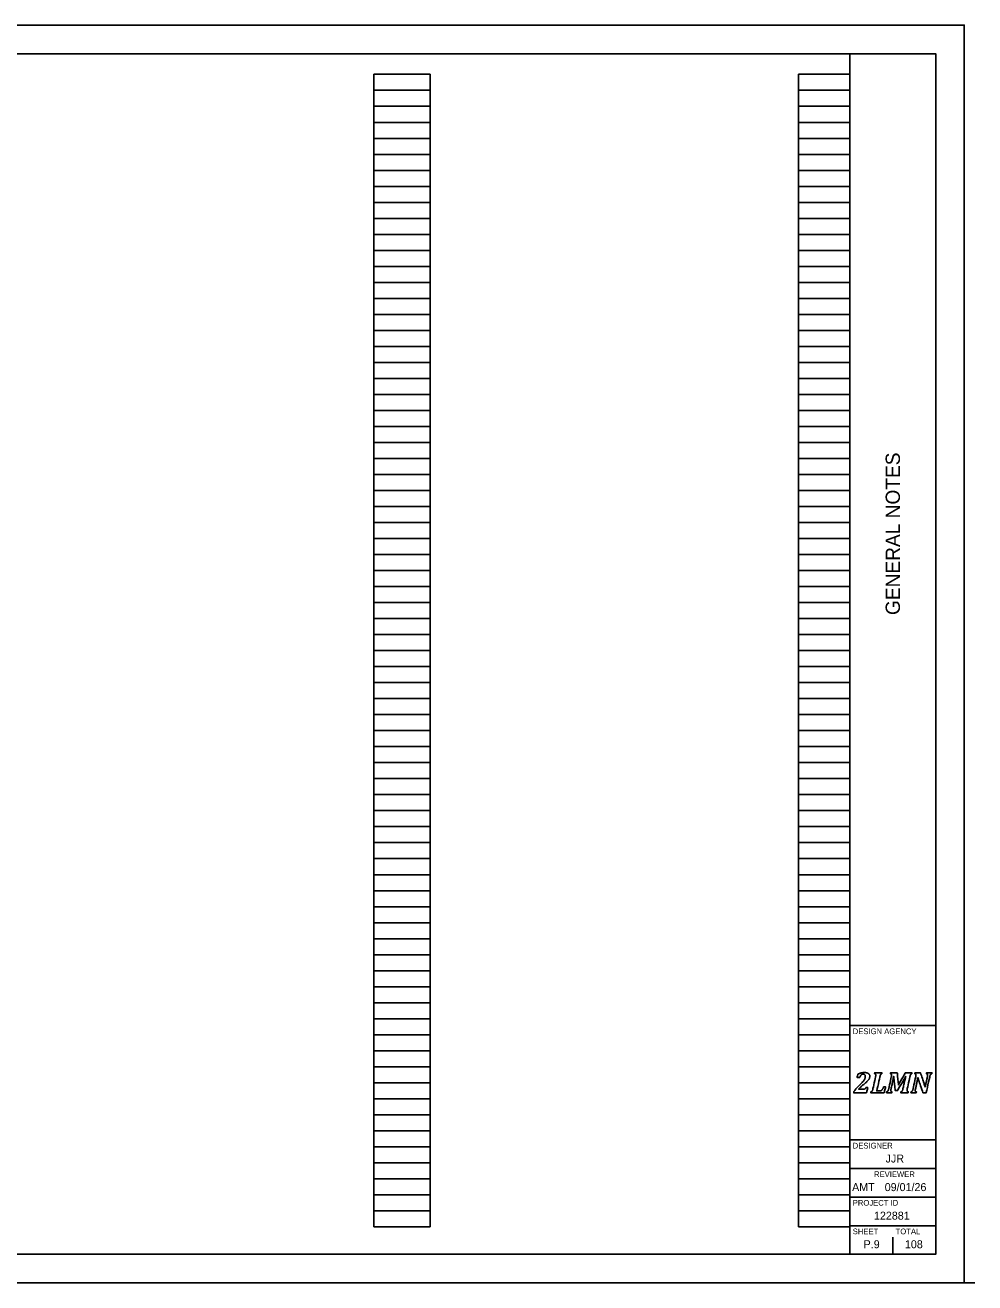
# Model space of a CAD drawing. Extents: x 0 to 34.2, y 0 to 22.
# Drawn here: x 17.58 to 34.18, y 0 to 22 of the extents above; entities that cross this region are included whole.
import ezdxf

# ---------------------------------------------------------------- set-up
doc = ezdxf.new("R2010")
doc.units = 0
for name, color, linetype in [('SH_Border', 7, 'Continuous'), ('SH_Cut_Line', 7, 'Continuous'), ('SH_Data', 7, 'Continuous'), ('SH_Text', 7, 'Continuous')]:
    doc.layers.add(name, color=color, linetype=linetype)

msp = doc.modelspace()

# ---------------------------------------------------------------- linework, layer by layer
at = {"layer": 'SH_Border'}
for p, q in [((32, 0.5), (32, 21.5)), ((32, 4.5), (33.5, 4.5)), ((32, 2.5), (33.5, 2.5)), ((32, 2), (33.5, 2)), ((32, 1.5), (33.5, 1.5)), ((32, 1), (33.5, 1))]:
    msp.add_line(p, q, dxfattribs=at)
msp.add_lwpolyline([(1.5, 21.5), (33.5, 21.5), (33.5, 0.5), (1.5, 0.5)], close=True, dxfattribs=at)
at = {"layer": 'SH_Cut_Line'}
msp.add_lwpolyline([(0, 0), (34, 0), (34, 22), (0, 22)], close=True, dxfattribs=at)
at = {"layer": 'SH_Data'}
for p, q in [((23.68, 0.98), (23.68, 21.14)), ((23.68, 21.14), (24.66, 21.14)), ((24.66, 0.98), (24.66, 21.14)), ((31.1, 0.98), (31.1, 21.14)), ((31.1, 21.14), (32, 21.14)), ((32, 0.98), (32, 21.14)), ((23.68, 20.86), (24.66, 20.86)), ((31.1, 20.86), (32, 20.86)), ((23.68, 20.58), (24.66, 20.58)), ((31.1, 20.58), (32, 20.58)), ((23.68, 20.3), (24.66, 20.3)), ((31.1, 20.3), (32, 20.3)), ((23.68, 20.02), (24.66, 20.02)), ((31.1, 20.02), (32, 20.02)), ((23.68, 19.74), (24.66, 19.74)), ((31.1, 19.74), (32, 19.74)), ((23.68, 19.46), (24.66, 19.46)), ((31.1, 19.46), (32, 19.46)), ((23.68, 19.18), (24.66, 19.18)), ((31.1, 19.18), (32, 19.18)), ((23.68, 18.9), (24.66, 18.9)), ((31.1, 18.9), (32, 18.9)), ((23.68, 18.62), (24.66, 18.62)), ((31.1, 18.62), (32, 18.62)), ((23.68, 18.34), (24.66, 18.34)), ((31.1, 18.34), (32, 18.34)), ((23.68, 18.06), (24.66, 18.06)), ((31.1, 18.06), (32, 18.06)), ((23.68, 17.78), (24.66, 17.78)), ((31.1, 17.78), (32, 17.78)), ((23.68, 17.5), (24.66, 17.5)), ((31.1, 17.5), (32, 17.5)), ((23.68, 17.22), (24.66, 17.22)), ((31.1, 17.22), (32, 17.22)), ((23.68, 16.94), (24.66, 16.94)), ((31.1, 16.94), (32, 16.94)), ((23.68, 16.66), (24.66, 16.66)), ((31.1, 16.66), (32, 16.66)), ((23.68, 16.38), (24.66, 16.38)), ((31.1, 16.38), (32, 16.38)), ((23.68, 16.1), (24.66, 16.1)), ((31.1, 16.1), (32, 16.1)), ((23.68, 15.82), (24.66, 15.82)), ((31.1, 15.82), (32, 15.82)), ((23.68, 15.54), (24.66, 15.54)), ((31.1, 15.54), (32, 15.54)), ((23.68, 15.26), (24.66, 15.26)), ((31.1, 15.26), (32, 15.26)), ((23.68, 14.98), (24.66, 14.98)), ((31.1, 14.98), (32, 14.98)), ((23.68, 14.7), (24.66, 14.7)), ((31.1, 14.7), (32, 14.7)), ((23.68, 14.42), (24.66, 14.42)), ((31.1, 14.42), (32, 14.42)), ((23.68, 14.14), (24.66, 14.14)), ((31.1, 14.14), (32, 14.14)), ((23.68, 13.86), (24.66, 13.86)), ((31.1, 13.86), (32, 13.86)), ((23.68, 13.58), (24.66, 13.58)), ((31.1, 13.58), (32, 13.58)), ((23.68, 13.3), (24.66, 13.3)), ((31.1, 13.3), (32, 13.3)), ((23.68, 13.02), (24.66, 13.02)), ((31.1, 13.02), (32, 13.02)), ((23.68, 12.74), (24.66, 12.74)), ((31.1, 12.74), (32, 12.74)), ((23.68, 12.46), (24.66, 12.46)), ((31.1, 12.46), (32, 12.46)), ((23.68, 12.18), (24.66, 12.18)), ((31.1, 12.18), (32, 12.18)), ((23.68, 11.9), (24.66, 11.9)), ((31.1, 11.9), (32, 11.9)), ((23.68, 11.62), (24.66, 11.62)), ((31.1, 11.62), (32, 11.62)), ((23.68, 11.34), (24.66, 11.34)), ((31.1, 11.34), (32, 11.34)), ((23.68, 11.06), (24.66, 11.06)), ((31.1, 11.06), (32, 11.06)), ((23.68, 10.78), (24.66, 10.78)), ((31.1, 10.78), (32, 10.78)), ((23.68, 10.5), (24.66, 10.5)), ((31.1, 10.5), (32, 10.5)), ((23.68, 10.22), (24.66, 10.22)), ((31.1, 10.22), (32, 10.22)), ((23.68, 9.94), (24.66, 9.94)), ((31.1, 9.94), (32, 9.94)), ((23.68, 9.66), (24.66, 9.66)), ((31.1, 9.66), (32, 9.66)), ((23.68, 9.38), (24.66, 9.38)), ((31.1, 9.38), (32, 9.38)), ((23.68, 9.1), (24.66, 9.1)), ((31.1, 9.1), (32, 9.1)), ((23.68, 8.82), (24.66, 8.82)), ((31.1, 8.82), (32, 8.82)), ((23.68, 8.54), (24.66, 8.54)), ((31.1, 8.54), (32, 8.54)), ((23.68, 8.26), (24.66, 8.26)), ((31.1, 8.26), (32, 8.26)), ((23.68, 7.98), (24.66, 7.98)), ((31.1, 7.98), (32, 7.98)), ((23.68, 7.7), (24.66, 7.7)), ((31.1, 7.7), (32, 7.7)), ((23.68, 7.42), (24.66, 7.42)), ((31.1, 7.42), (32, 7.42)), ((23.68, 7.14), (24.66, 7.14)), ((31.1, 7.14), (32, 7.14)), ((23.68, 6.86), (24.66, 6.86)), ((31.1, 6.86), (32, 6.86)), ((23.68, 6.58), (24.66, 6.58)), ((31.1, 6.58), (32, 6.58)), ((23.68, 6.3), (24.66, 6.3)), ((31.1, 6.3), (32, 6.3)), ((23.68, 6.02), (24.66, 6.02)), ((31.1, 6.02), (32, 6.02)), ((23.68, 5.74), (24.66, 5.74)), ((31.1, 5.74), (32, 5.74)), ((23.68, 5.46), (24.66, 5.46)), ((31.1, 5.46), (32, 5.46)), ((23.68, 5.18), (24.66, 5.18)), ((31.1, 5.18), (32, 5.18)), ((23.68, 4.9), (24.66, 4.9)), ((31.1, 4.9), (32, 4.9)), ((23.68, 4.62), (24.66, 4.62)), ((31.1, 4.62), (32, 4.62)), ((23.68, 4.34), (24.66, 4.34)), ((31.1, 4.34), (32, 4.34)), ((23.68, 4.06), (24.66, 4.06)), ((31.1, 4.06), (32, 4.06)), ((23.68, 3.78), (24.66, 3.78)), ((31.1, 3.78), (32, 3.78)), ((23.68, 3.5), (24.66, 3.5)), ((31.1, 3.5), (32, 3.5)), ((32.75, 3.5), (32.75, 3.5)), ((23.68, 3.22), (24.66, 3.22)), ((31.1, 3.22), (32, 3.22)), ((23.68, 2.94), (24.66, 2.94)), ((31.1, 2.94), (32, 2.94)), ((23.68, 2.66), (24.66, 2.66)), ((31.1, 2.66), (32, 2.66)), ((23.68, 2.38), (24.66, 2.38)), ((31.1, 2.38), (32, 2.38)), ((23.68, 2.1), (24.66, 2.1)), ((31.1, 2.1), (32, 2.1)), ((23.68, 1.82), (24.66, 1.82)), ((31.1, 1.82), (32, 1.82)), ((23.68, 1.54), (24.66, 1.54)), ((31.1, 1.54), (32, 1.54)), ((23.68, 1.26), (24.66, 1.26)), ((31.1, 1.26), (32, 1.26)), ((23.68, 0.98), (24.66, 0.98)), ((31.1, 0.98), (32, 0.98)), ((32.375, 0.675), (32.375, 0.675)), ((32.75, 0.5), (32.75, 0.8))]:
    msp.add_line(p, q, dxfattribs=at)
for points in [[(32.237, 3.388), (32.246, 3.388), (32.253, 3.389), (32.258, 3.39), (32.263, 3.392), (32.267, 3.394), (32.27, 3.397), (32.273, 3.401), (32.277, 3.408), (32.281, 3.417), (32.281, 3.417), (32.312, 3.417), (32.312, 3.417), (32.312, 3.417), (32.29, 3.326), (32.29, 3.326), (32.29, 3.326), (32.066, 3.326), (32.066, 3.326), (32.066, 3.326), (32.069, 3.343), (32.069, 3.343), (32.078, 3.358), (32.091, 3.375), (32.106, 3.394), (32.122, 3.412), (32.144, 3.435), (32.172, 3.462), (32.197, 3.486), (32.217, 3.506), (32.23, 3.521), (32.243, 3.537), (32.253, 3.551), (32.259, 3.566), (32.266, 3.58), (32.269, 3.595), (32.269, 3.61), (32.269, 3.622), (32.266, 3.632), (32.26, 3.64), (32.253, 3.647), (32.245, 3.65), (32.234, 3.65), (32.22, 3.65), (32.208, 3.646), (32.198, 3.636), (32.188, 3.627), (32.18, 3.613), (32.172, 3.593), (32.172, 3.593), (32.126, 3.593), (32.126, 3.593), (32.126, 3.593), (32.14, 3.654), (32.14, 3.654), (32.166, 3.663), (32.188, 3.669), (32.205, 3.673), (32.223, 3.676), (32.24, 3.678), (32.258, 3.678), (32.278, 3.678), (32.295, 3.675), (32.309, 3.669), (32.322, 3.664), (32.332, 3.656), (32.339, 3.646), (32.345, 3.637), (32.348, 3.626), (32.348, 3.613), (32.348, 3.602), (32.346, 3.591), (32.342, 3.581), (32.339, 3.571), (32.333, 3.56), (32.324, 3.549), (32.315, 3.539), (32.304, 3.526), (32.289, 3.513), (32.275, 3.499), (32.254, 3.482), (32.228, 3.46), (32.216, 3.45), (32.202, 3.438), (32.188, 3.425), (32.174, 3.412), (32.162, 3.4), (32.154, 3.391), (32.154, 3.391), (32.153, 3.388), (32.153, 3.388), (32.153, 3.388), (32.237, 3.388), (32.237, 3.388)], [(32.237, 3.388), (32.237, 3.388), (32.153, 3.388), (32.153, 3.388), (32.153, 3.388), (32.154, 3.391), (32.154, 3.391), (32.162, 3.4), (32.174, 3.412), (32.188, 3.425), (32.202, 3.438), (32.216, 3.45), (32.228, 3.46), (32.254, 3.482), (32.275, 3.499), (32.289, 3.513), (32.304, 3.526), (32.315, 3.539), (32.324, 3.549), (32.333, 3.56), (32.339, 3.571), (32.342, 3.581), (32.346, 3.591), (32.348, 3.602), (32.348, 3.613), (32.348, 3.626), (32.345, 3.637), (32.339, 3.646), (32.332, 3.656), (32.322, 3.664), (32.309, 3.669), (32.295, 3.675), (32.278, 3.678), (32.258, 3.678), (32.24, 3.678), (32.223, 3.676), (32.205, 3.673), (32.188, 3.669), (32.166, 3.663), (32.14, 3.654), (32.14, 3.654), (32.126, 3.593), (32.126, 3.593), (32.126, 3.593), (32.172, 3.593), (32.172, 3.593), (32.18, 3.613), (32.188, 3.627), (32.198, 3.636), (32.208, 3.646), (32.22, 3.65), (32.234, 3.65), (32.245, 3.65), (32.253, 3.647), (32.26, 3.64), (32.266, 3.632), (32.269, 3.622), (32.269, 3.61), (32.269, 3.595), (32.266, 3.58), (32.259, 3.566), (32.253, 3.551), (32.243, 3.537), (32.23, 3.521), (32.217, 3.506), (32.197, 3.486), (32.172, 3.462), (32.144, 3.435), (32.122, 3.412), (32.106, 3.394), (32.091, 3.375), (32.078, 3.358), (32.069, 3.343), (32.069, 3.343), (32.066, 3.326), (32.066, 3.326), (32.066, 3.326), (32.29, 3.326), (32.29, 3.326), (32.29, 3.326), (32.312, 3.417), (32.312, 3.417), (32.312, 3.417), (32.281, 3.417), (32.281, 3.417), (32.277, 3.408), (32.273, 3.401), (32.27, 3.397), (32.267, 3.394), (32.263, 3.392), (32.258, 3.39), (32.253, 3.389), (32.246, 3.388), (32.237, 3.388)], [(32.518, 3.356), (32.527, 3.356), (32.533, 3.357), (32.538, 3.358), (32.542, 3.36), (32.546, 3.362), (32.55, 3.365), (32.554, 3.368), (32.558, 3.372), (32.562, 3.377), (32.567, 3.382), (32.571, 3.388), (32.576, 3.397), (32.58, 3.405), (32.585, 3.415), (32.589, 3.427), (32.589, 3.427), (32.624, 3.427), (32.624, 3.427), (32.624, 3.427), (32.598, 3.326), (32.598, 3.326), (32.598, 3.326), (32.365, 3.326), (32.365, 3.326), (32.365, 3.326), (32.369, 3.343), (32.369, 3.343), (32.376, 3.345), (32.381, 3.348), (32.385, 3.351), (32.389, 3.355), (32.392, 3.36), (32.395, 3.366), (32.398, 3.373), (32.4, 3.382), (32.403, 3.395), (32.403, 3.395), (32.449, 3.605), (32.449, 3.605), (32.452, 3.615), (32.453, 3.625), (32.453, 3.635), (32.453, 3.642), (32.451, 3.647), (32.448, 3.651), (32.444, 3.654), (32.439, 3.656), (32.432, 3.657), (32.432, 3.657), (32.435, 3.674), (32.435, 3.674), (32.435, 3.674), (32.563, 3.674), (32.563, 3.674), (32.563, 3.674), (32.559, 3.657), (32.559, 3.657), (32.552, 3.655), (32.547, 3.652), (32.543, 3.649), (32.539, 3.645), (32.536, 3.64), (32.533, 3.634), (32.531, 3.627), (32.528, 3.618), (32.525, 3.605), (32.525, 3.605), (32.47, 3.356), (32.47, 3.356), (32.47, 3.356), (32.518, 3.356), (32.518, 3.356)], [(32.518, 3.356), (32.518, 3.356), (32.47, 3.356), (32.47, 3.356), (32.47, 3.356), (32.525, 3.605), (32.525, 3.605), (32.528, 3.618), (32.531, 3.627), (32.533, 3.634), (32.536, 3.64), (32.539, 3.645), (32.543, 3.649), (32.547, 3.652), (32.552, 3.655), (32.559, 3.657), (32.559, 3.657), (32.563, 3.674), (32.563, 3.674), (32.563, 3.674), (32.435, 3.674), (32.435, 3.674), (32.435, 3.674), (32.432, 3.657), (32.432, 3.657), (32.439, 3.656), (32.444, 3.654), (32.448, 3.651), (32.451, 3.647), (32.453, 3.642), (32.453, 3.635), (32.453, 3.625), (32.452, 3.615), (32.449, 3.605), (32.449, 3.605), (32.403, 3.395), (32.403, 3.395), (32.4, 3.382), (32.398, 3.373), (32.395, 3.366), (32.392, 3.36), (32.389, 3.355), (32.385, 3.351), (32.381, 3.348), (32.376, 3.345), (32.369, 3.343), (32.369, 3.343), (32.365, 3.326), (32.365, 3.326), (32.365, 3.326), (32.598, 3.326), (32.598, 3.326), (32.598, 3.326), (32.624, 3.427), (32.624, 3.427), (32.624, 3.427), (32.589, 3.427), (32.589, 3.427), (32.585, 3.415), (32.58, 3.405), (32.576, 3.397), (32.571, 3.388), (32.567, 3.382), (32.562, 3.377), (32.558, 3.372), (32.554, 3.368), (32.55, 3.365), (32.546, 3.362), (32.542, 3.36), (32.538, 3.358), (32.533, 3.357), (32.527, 3.356), (32.518, 3.356)], [(32.829, 3.674), (32.829, 3.674), (32.849, 3.461), (32.849, 3.461), (32.849, 3.461), (32.969, 3.674), (32.969, 3.674), (32.969, 3.674), (33.087, 3.674), (33.087, 3.674), (33.087, 3.674), (33.084, 3.657), (33.084, 3.657), (33.077, 3.655), (33.071, 3.652), (33.067, 3.649), (33.064, 3.645), (33.06, 3.64), (33.058, 3.634), (33.055, 3.627), (33.052, 3.618), (33.05, 3.605), (33.05, 3.605), (33.003, 3.395), (33.003, 3.395), (33.002, 3.39), (33.002, 3.387), (33.001, 3.384), (33.001, 3.382), (33.001, 3.379), (33, 3.376), (33, 3.373), (33, 3.369), (33, 3.365), (33, 3.358), (33.002, 3.353), (33.005, 3.349), (33.008, 3.346), (33.014, 3.344), (33.021, 3.343), (33.021, 3.343), (33.018, 3.326), (33.018, 3.326), (33.018, 3.326), (32.89, 3.326), (32.89, 3.326), (32.89, 3.326), (32.893, 3.343), (32.893, 3.343), (32.9, 3.345), (32.906, 3.348), (32.91, 3.351), (32.914, 3.355), (32.917, 3.36), (32.919, 3.366), (32.922, 3.373), (32.925, 3.382), (32.928, 3.395), (32.928, 3.395), (32.951, 3.502), (32.951, 3.502), (32.954, 3.513), (32.957, 3.529), (32.962, 3.548), (32.967, 3.568), (32.972, 3.588), (32.978, 3.609), (32.978, 3.609), (32.973, 3.609), (32.973, 3.609), (32.965, 3.594), (32.957, 3.579), (32.948, 3.563), (32.948, 3.563), (32.833, 3.364), (32.833, 3.364), (32.833, 3.364), (32.792, 3.364), (32.792, 3.364), (32.792, 3.364), (32.775, 3.518), (32.775, 3.518), (32.773, 3.537), (32.772, 3.554), (32.77, 3.569), (32.769, 3.583), (32.768, 3.597), (32.768, 3.611), (32.768, 3.611), (32.764, 3.611), (32.764, 3.611), (32.761, 3.596), (32.758, 3.578), (32.755, 3.558), (32.751, 3.538), (32.747, 3.521), (32.744, 3.507), (32.744, 3.507), (32.72, 3.395), (32.72, 3.395), (32.719, 3.39), (32.718, 3.387), (32.718, 3.384), (32.717, 3.382), (32.717, 3.379), (32.717, 3.376), (32.717, 3.373), (32.716, 3.369), (32.716, 3.365), (32.716, 3.358), (32.718, 3.353), (32.721, 3.349), (32.725, 3.346), (32.73, 3.344), (32.738, 3.343), (32.738, 3.343), (32.734, 3.326), (32.734, 3.326), (32.734, 3.326), (32.641, 3.326), (32.641, 3.326), (32.641, 3.326), (32.644, 3.343), (32.644, 3.343), (32.651, 3.345), (32.657, 3.348), (32.661, 3.351), (32.665, 3.355), (32.668, 3.36), (32.67, 3.366), (32.673, 3.373), (32.676, 3.382), (32.679, 3.395), (32.679, 3.395), (32.725, 3.605), (32.725, 3.605), (32.727, 3.615), (32.728, 3.625), (32.728, 3.635), (32.728, 3.642), (32.727, 3.647), (32.723, 3.651), (32.72, 3.654), (32.715, 3.656), (32.707, 3.657), (32.707, 3.657), (32.711, 3.674), (32.711, 3.674), (32.711, 3.674), (32.829, 3.674), (32.829, 3.674)], [(32.829, 3.674), (32.829, 3.674), (32.711, 3.674), (32.711, 3.674), (32.711, 3.674), (32.707, 3.657), (32.707, 3.657), (32.715, 3.656), (32.72, 3.654), (32.723, 3.651), (32.727, 3.647), (32.728, 3.642), (32.728, 3.635), (32.728, 3.625), (32.727, 3.615), (32.725, 3.605), (32.725, 3.605), (32.679, 3.395), (32.679, 3.395), (32.676, 3.382), (32.673, 3.373), (32.67, 3.366), (32.668, 3.36), (32.665, 3.355), (32.661, 3.351), (32.657, 3.348), (32.651, 3.345), (32.644, 3.343), (32.644, 3.343), (32.641, 3.326), (32.641, 3.326), (32.641, 3.326), (32.734, 3.326), (32.734, 3.326), (32.734, 3.326), (32.738, 3.343), (32.738, 3.343), (32.73, 3.344), (32.725, 3.346), (32.721, 3.349), (32.718, 3.353), (32.716, 3.358), (32.716, 3.365), (32.716, 3.369), (32.717, 3.373), (32.717, 3.376), (32.717, 3.379), (32.717, 3.382), (32.718, 3.384), (32.718, 3.387), (32.719, 3.39), (32.72, 3.395), (32.72, 3.395), (32.744, 3.507), (32.744, 3.507), (32.747, 3.521), (32.751, 3.538), (32.755, 3.558), (32.758, 3.578), (32.761, 3.596), (32.764, 3.611), (32.764, 3.611), (32.768, 3.611), (32.768, 3.611), (32.768, 3.597), (32.769, 3.583), (32.77, 3.569), (32.772, 3.554), (32.773, 3.537), (32.775, 3.518), (32.775, 3.518), (32.792, 3.364), (32.792, 3.364), (32.792, 3.364), (32.833, 3.364), (32.833, 3.364), (32.833, 3.364), (32.948, 3.563), (32.948, 3.563), (32.957, 3.579), (32.965, 3.594), (32.973, 3.609), (32.973, 3.609), (32.978, 3.609), (32.978, 3.609), (32.972, 3.588), (32.967, 3.568), (32.962, 3.548), (32.957, 3.529), (32.954, 3.513), (32.951, 3.502), (32.951, 3.502), (32.928, 3.395), (32.928, 3.395), (32.925, 3.382), (32.922, 3.373), (32.919, 3.366), (32.917, 3.36), (32.914, 3.355), (32.91, 3.351), (32.906, 3.348), (32.9, 3.345), (32.893, 3.343), (32.893, 3.343), (32.89, 3.326), (32.89, 3.326), (32.89, 3.326), (33.018, 3.326), (33.018, 3.326), (33.018, 3.326), (33.021, 3.343), (33.021, 3.343), (33.014, 3.344), (33.008, 3.346), (33.005, 3.349), (33.002, 3.353), (33, 3.358), (33, 3.365), (33, 3.369), (33, 3.373), (33, 3.376), (33.001, 3.379), (33.001, 3.382), (33.001, 3.384), (33.002, 3.387), (33.002, 3.39), (33.003, 3.395), (33.003, 3.395), (33.05, 3.605), (33.05, 3.605), (33.052, 3.618), (33.055, 3.627), (33.058, 3.634), (33.06, 3.64), (33.064, 3.645), (33.067, 3.649), (33.071, 3.652), (33.077, 3.655), (33.084, 3.657), (33.084, 3.657), (33.087, 3.674), (33.087, 3.674), (33.087, 3.674), (32.969, 3.674), (32.969, 3.674), (32.969, 3.674), (32.849, 3.461), (32.849, 3.461), (32.849, 3.461), (32.829, 3.674), (32.829, 3.674)], [(33.137, 3.674), (33.137, 3.674), (33.234, 3.674), (33.234, 3.674), (33.234, 3.674), (33.283, 3.53), (33.283, 3.53), (33.296, 3.49), (33.307, 3.456), (33.315, 3.426), (33.315, 3.426), (33.318, 3.426), (33.318, 3.426), (33.323, 3.455), (33.329, 3.488), (33.337, 3.523), (33.337, 3.523), (33.355, 3.605), (33.355, 3.605), (33.357, 3.615), (33.358, 3.625), (33.358, 3.635), (33.358, 3.642), (33.357, 3.647), (33.353, 3.651), (33.35, 3.654), (33.345, 3.656), (33.337, 3.657), (33.337, 3.657), (33.341, 3.674), (33.341, 3.674), (33.341, 3.674), (33.434, 3.674), (33.434, 3.674), (33.434, 3.674), (33.431, 3.657), (33.431, 3.657), (33.424, 3.655), (33.418, 3.652), (33.414, 3.649), (33.41, 3.645), (33.407, 3.64), (33.405, 3.634), (33.402, 3.627), (33.399, 3.618), (33.396, 3.605), (33.396, 3.605), (33.335, 3.326), (33.335, 3.326), (33.335, 3.326), (33.277, 3.326), (33.277, 3.326), (33.277, 3.326), (33.216, 3.504), (33.216, 3.504), (33.211, 3.518), (33.207, 3.531), (33.204, 3.543), (33.2, 3.556), (33.195, 3.571), (33.19, 3.59), (33.19, 3.59), (33.186, 3.59), (33.186, 3.59), (33.185, 3.579), (33.182, 3.563), (33.179, 3.543), (33.175, 3.523), (33.17, 3.501), (33.165, 3.478), (33.165, 3.478), (33.147, 3.395), (33.147, 3.395), (33.146, 3.39), (33.145, 3.387), (33.145, 3.384), (33.144, 3.382), (33.144, 3.379), (33.144, 3.376), (33.143, 3.373), (33.143, 3.369), (33.143, 3.365), (33.143, 3.358), (33.145, 3.353), (33.148, 3.349), (33.152, 3.346), (33.157, 3.344), (33.164, 3.343), (33.164, 3.343), (33.161, 3.326), (33.161, 3.326), (33.161, 3.326), (33.067, 3.326), (33.067, 3.326), (33.067, 3.326), (33.071, 3.343), (33.071, 3.343), (33.078, 3.345), (33.083, 3.348), (33.087, 3.351), (33.091, 3.355), (33.094, 3.36), (33.097, 3.366), (33.1, 3.373), (33.102, 3.382), (33.105, 3.395), (33.105, 3.395), (33.151, 3.605), (33.151, 3.605), (33.154, 3.615), (33.155, 3.625), (33.155, 3.635), (33.155, 3.642), (33.153, 3.647), (33.15, 3.651), (33.146, 3.654), (33.141, 3.656), (33.134, 3.657), (33.134, 3.657), (33.137, 3.674), (33.137, 3.674)], [(33.137, 3.674), (33.137, 3.674), (33.134, 3.657), (33.134, 3.657), (33.141, 3.656), (33.146, 3.654), (33.15, 3.651), (33.153, 3.647), (33.155, 3.642), (33.155, 3.635), (33.155, 3.625), (33.154, 3.615), (33.151, 3.605), (33.151, 3.605), (33.105, 3.395), (33.105, 3.395), (33.102, 3.382), (33.1, 3.373), (33.097, 3.366), (33.094, 3.36), (33.091, 3.355), (33.087, 3.351), (33.083, 3.348), (33.078, 3.345), (33.071, 3.343), (33.071, 3.343), (33.067, 3.326), (33.067, 3.326), (33.067, 3.326), (33.161, 3.326), (33.161, 3.326), (33.161, 3.326), (33.164, 3.343), (33.164, 3.343), (33.157, 3.344), (33.152, 3.346), (33.148, 3.349), (33.145, 3.353), (33.143, 3.358), (33.143, 3.365), (33.143, 3.369), (33.143, 3.373), (33.144, 3.376), (33.144, 3.379), (33.144, 3.382), (33.145, 3.384), (33.145, 3.387), (33.146, 3.39), (33.147, 3.395), (33.147, 3.395), (33.165, 3.478), (33.165, 3.478), (33.17, 3.501), (33.175, 3.523), (33.179, 3.543), (33.182, 3.563), (33.185, 3.579), (33.186, 3.59), (33.186, 3.59), (33.19, 3.59), (33.19, 3.59), (33.195, 3.571), (33.2, 3.556), (33.204, 3.543), (33.207, 3.531), (33.211, 3.518), (33.216, 3.504), (33.216, 3.504), (33.277, 3.326), (33.277, 3.326), (33.277, 3.326), (33.335, 3.326), (33.335, 3.326), (33.335, 3.326), (33.396, 3.605), (33.396, 3.605), (33.399, 3.618), (33.402, 3.627), (33.405, 3.634), (33.407, 3.64), (33.41, 3.645), (33.414, 3.649), (33.418, 3.652), (33.424, 3.655), (33.431, 3.657), (33.431, 3.657), (33.434, 3.674), (33.434, 3.674), (33.434, 3.674), (33.341, 3.674), (33.341, 3.674), (33.341, 3.674), (33.337, 3.657), (33.337, 3.657), (33.345, 3.656), (33.35, 3.654), (33.353, 3.651), (33.357, 3.647), (33.358, 3.642), (33.358, 3.635), (33.358, 3.625), (33.357, 3.615), (33.355, 3.605), (33.355, 3.605), (33.337, 3.523), (33.337, 3.523), (33.329, 3.488), (33.323, 3.455), (33.318, 3.426), (33.318, 3.426), (33.315, 3.426), (33.315, 3.426), (33.307, 3.456), (33.296, 3.49), (33.283, 3.53), (33.283, 3.53), (33.234, 3.674), (33.234, 3.674), (33.234, 3.674), (33.137, 3.674), (33.137, 3.674)]]:
    msp.add_open_spline(points, degree=3, dxfattribs=at)
at = {"layer": 'SH_Text'}
msp.add_line((0, 0), (34.184, 0), dxfattribs=at)

# ---------------------------------------------------------------- texts
at = {"layer": 'SH_Data'}
msp.add_text('GENERAL NOTES', height=0.25, rotation=90, dxfattribs=at).set_placement((32.875, 11.682))
for s, height, p in [('DESIGN AGENCY', 0.1, (32.05, 4.35)), ('DESIGNER', 0.1, (32.05, 2.35)), ('JJR', 0.14, (32.624, 2.105)), ('REVIEWER', 0.1, (32.422, 1.85)), ('AMT', 0.14, (32.039, 1.605)), ('09/01/26', 0.14, (32.609, 1.605)), ('PROJECT ID', 0.1, (32.05, 1.35)), ('122881', 0.14, (32.421, 1.105)), ('SHEET', 0.1, (32.05, 0.85)), ('TOTAL', 0.1, (32.8, 0.85)), ('P.9', 0.14, (32.24, 0.605)), ('108', 0.14, (32.962, 0.605))]:
    msp.add_text(s, height=height, dxfattribs=at).set_placement(p)

doc.saveas('drawing.dxf')
